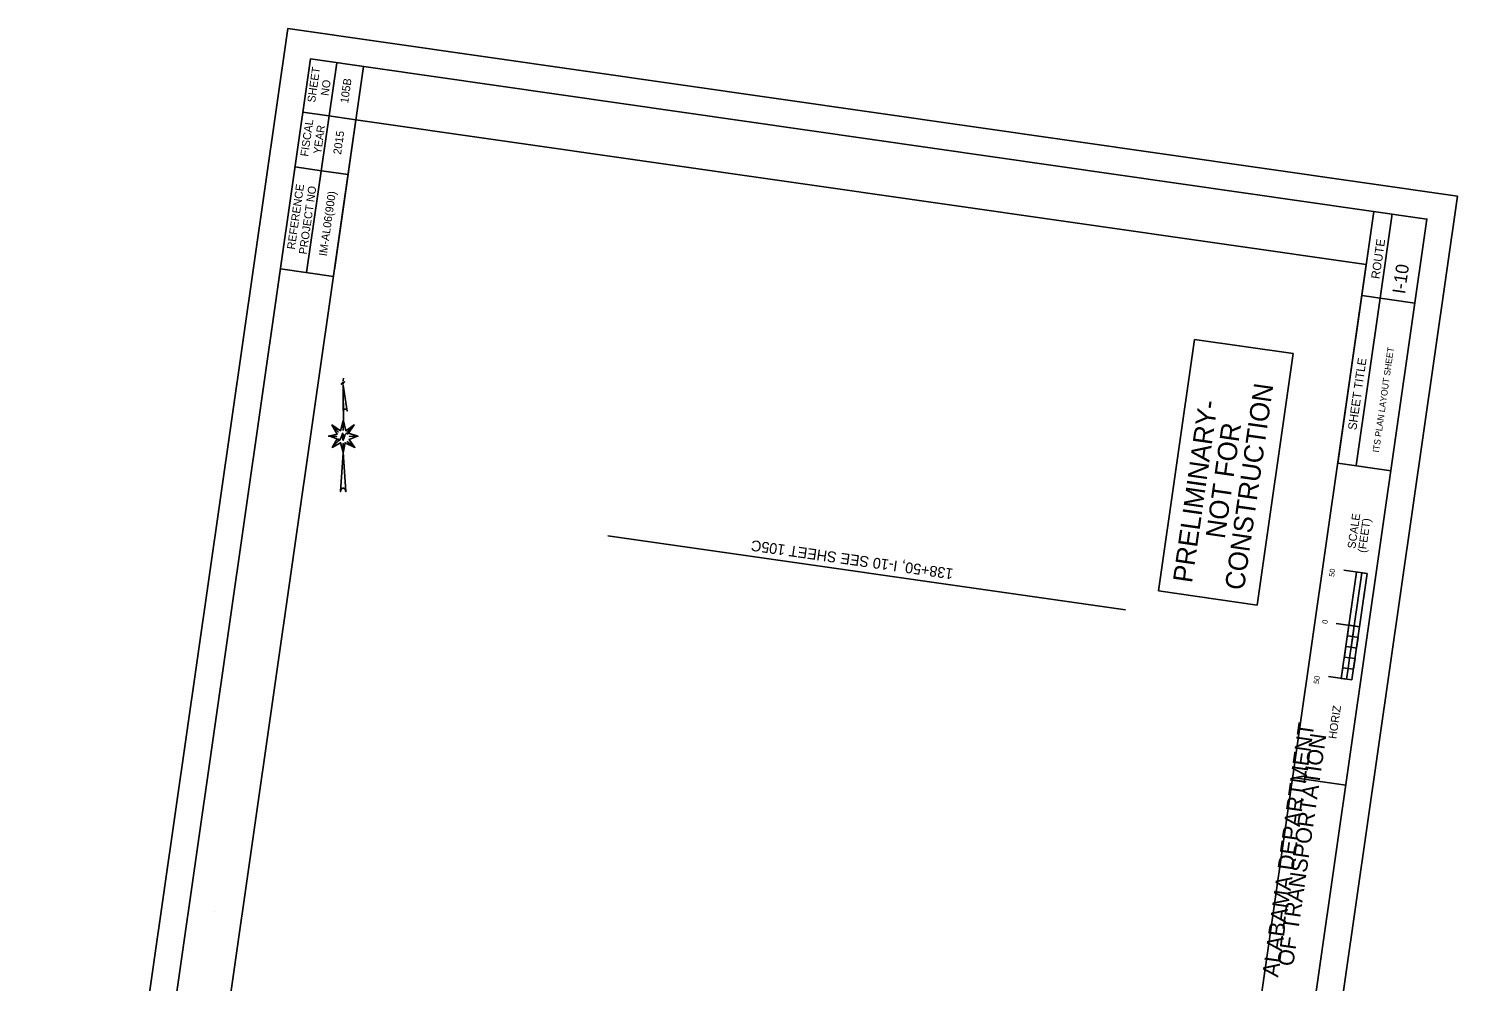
# Model space of a CAD drawing. Extents: x 1797106 to 1798436, y 247408 to 249247.
# Drawn here: x 1797106 to 1798436, y 248360 to 249247 of the extents above; entities that cross this region are included whole.
import ezdxf

# ---------------------------------------------------------------- set-up
doc = ezdxf.new("R2010")
doc.units = 0
for name, color, linetype in [('1', 7, 'Continuous'), ('29', 7, 'Continuous'), ('ANNO-SHT', 7, 'Continuous'), ('ANNO-SYMB', 7, 'Continuous'), ('ANNO-TXT', 7, 'Continuous'), ('DRAINAGE', 7, 'Continuous'), ('Level 1', 7, 'Continuous'), ('Level 57', 7, 'Continuous'), ('Level 6', 7, 'Continuous'), ('Level 62', 7, 'Continuous'), ('SHT-BDR', 7, 'Continuous'), ('SHT-BNDRY', 7, 'Continuous')]:
    doc.layers.add(name, color=color, linetype=linetype)

# ---------------------------------------------------------------- blocks, each defined once
blk = doc.blocks.new('SC47208')
at = {"layer": 'Level 1'}
blk.add_line((0, 0), (0, 0), dxfattribs=at)

msp = doc.modelspace()

# ---------------------------------------------------------------- linework, layer by layer
at = {"layer": '1'}
msp.add_lwpolyline([(1798158, 248723.5), (1798191.5, 248957.5), (1798283.2, 248944.4), (1798249.7, 248710.3)], close=True, dxfattribs=at)
at = {"layer": '29'}
msp.add_lwpolyline([(1797645.4, 248774.8), (1798127.1, 248706)], dxfattribs=at)
at = {"layer": 'ANNO-SYMB'}
for p, q in [((1798342.3, 248741), (1798328.1, 248642)), ((1798352.2, 248739.6), (1798330.4, 248742.7)), ((1798352.2, 248739.6), (1798338, 248640.6)), ((1798352.2, 248739.6), (1798347.3, 248740.3)), ((1798352.2, 248739.6), (1798347.3, 248740.3)), ((1798352.2, 248739.6), (1798347.3, 248740.3)), ((1798345.1, 248690.1), (1798323.3, 248693.2)), ((1798345.1, 248690.1), (1798323.3, 248693.2)), ((1798345.1, 248690.1), (1798323.3, 248693.2)), ((1798340.2, 248690.8), (1798335.2, 248691.5)), ((1798340.2, 248690.8), (1798335.2, 248691.5)), ((1798340.2, 248690.8), (1798335.2, 248691.5)), ((1798340.2, 248690.8), (1798337.3, 248671)), ((1798338, 248640.6), (1798316.3, 248643.8)), ((1798334.5, 248651.2), (1798329.5, 248651.9)), ((1798334.5, 248651.2), (1798329.5, 248651.9))]:
    msp.add_line(p, q, dxfattribs=at)
for points in [[(1798340.2, 248690.8), (1798347.3, 248740.3), (1798352.2, 248739.6), (1798345.1, 248690.1)], [(1798333.8, 248681.6), (1798335.2, 248691.5), (1798340.2, 248690.8), (1798338.8, 248680.9)], [(1798337.3, 248671), (1798338.8, 248680.9), (1798343.7, 248680.2), (1798342.3, 248670.3)], [(1798331, 248661.8), (1798332.4, 248671.7), (1798337.3, 248671), (1798335.9, 248661.1)], [(1798334.5, 248651.2), (1798335.9, 248661.1), (1798340.9, 248660.4), (1798339.4, 248650.5)], [(1798328.1, 248642), (1798329.5, 248651.9), (1798334.5, 248651.2), (1798333.1, 248641.3)]]:
    msp.add_lwpolyline(points, close=True, dxfattribs=at)
at = {"layer": 'ANNO-TXT'}
for p, q in [((1798364.4, 248996.1), (1798375.6, 249074.4)), ((1798342, 248840.1), (1798364.4, 248996.1))]:
    msp.add_line(p, q, dxfattribs=at)
at = {"layer": 'Level 57'}
msp.add_line((1797399.2, 248921.6), (1797399, 248919.1), dxfattribs=at)
for points in [[(1797400.3, 248918), (1797400.2, 248918), (1797400.2, 248917.8), (1797400.3, 248918), (1797400.3, 248918.1), (1797400.1, 248918.1), (1797399.8, 248918), (1797399.7, 248917.9), (1797399.5, 248917.5), (1797399.4, 248917.1), (1797399.1, 248916.5), (1797399.1, 248916.4), (1797399, 248916), (1797399, 248916.6), (1797398.9, 248917.5), (1797398.7, 248918.1), (1797398.7, 248917.5), (1797399, 248916), (1797398.9, 248917.5), (1797398.7, 248918.1), (1797398.6, 248917.6), (1797398.2, 248916.5), (1797397.9, 248916), (1797397.7, 248915.9), (1797397.4, 248915.9), (1797397.3, 248916), (1797397.3, 248916.2), (1797397.4, 248916.3), (1797397.5, 248916.2), (1797397.4, 248916.1)], [(1797399, 248915.1), (1797402.7, 248890.9), (1797402.6, 248891.7), (1797402.4, 248892), (1797402, 248892.3), (1797401.5, 248892.6), (1797401.1, 248892.6), (1797400.8, 248892.6), (1797400.4, 248892.7), (1797400.1, 248892.5), (1797399.8, 248892.4), (1797399.4, 248892.1), (1797399.2, 248891.9), (1797399.1, 248891.6), (1797399.1, 248891.4), (1797399.1, 248914.9), (1797399.2, 248882)], [(1797399.1, 248882), (1797399, 248873.1), (1797399.1, 248882.1), (1797396.4, 248872.5), (1797388.5, 248878), (1797394.6, 248871.3), (1797388.5, 248878), (1797393.5, 248869.5), (1797385.5, 248867.5), (1797393.1, 248867.3), (1797385.6, 248867.7), (1797393.3, 248864.9), (1797388.8, 248857), (1797394.5, 248862.8), (1797388.8, 248857), (1797396.6, 248861.4), (1797399, 248852.5), (1797398.9, 248860.8), (1797399, 248852.3), (1797401, 248861.3), (1797409.9, 248857.1), (1797400.9, 248861.3), (1797399, 248852), (1797396.6, 248816), (1797396.8, 248817.2), (1797397.1, 248818), (1797397.6, 248818.5), (1797398.2, 248818.9), (1797398.8, 248819), (1797399.4, 248819), (1797399.9, 248818.8), (1797400.4, 248818.5), (1797400.8, 248818), (1797401.2, 248817.4), (1797401.3, 248816.9), (1797401.5, 248816), (1797399.1, 248852.5), (1797400.8, 248861.4), (1797409.8, 248857.1), (1797403, 248862.4), (1797409.6, 248857.3), (1797404.5, 248864.3), (1797412.5, 248867.4), (1797404.8, 248867.3), (1797412.7, 248867.4), (1797403.9, 248870.2), (1797409.4, 248878), (1797403, 248871.7), (1797409.4, 248878), (1797401.4, 248872.5), (1797399.2, 248881.9)], [(1797403, 248870), (1797402.7, 248869.8), (1797403.1, 248869.5), (1797403.2, 248869.9), (1797403.1, 248870.2), (1797403, 248870.4), (1797402.3, 248870.3), (1797401.8, 248870), (1797400.7, 248868.8), (1797400.6, 248868.3), (1797400.3, 248867.1), (1797399.8, 248865.9), (1797399.3, 248865), (1797399.1, 248863.6), (1797399.1, 248865.4), (1797399, 248867.6), (1797398.9, 248868.8), (1797398.4, 248870.2), (1797398.3, 248868.5), (1797398.6, 248866.3), (1797398.8, 248864.8), (1797399.1, 248863.7), (1797399.1, 248865.7), (1797398.9, 248868.8), (1797398.3, 248870.3), (1797398, 248868.8), (1797397.4, 248867.2), (1797397.1, 248866.5), (1797396.9, 248865.7), (1797396.5, 248864.9), (1797396.2, 248864.4), (1797395.9, 248863.8), (1797395.1, 248863.5), (1797394.5, 248863.6), (1797394.2, 248863.9), (1797394.2, 248864.6), (1797394.6, 248864.9), (1797394.9, 248864.5), (1797394.6, 248864.3)]]:
    msp.add_lwpolyline(points, dxfattribs=at)
at = {"layer": 'Level 6'}
for p, q in [((1797393, 249215.2), (1797365, 249019.9)), ((1797418, 249211.6), (1797390.9, 249022.3)), ((1797385.6, 249165.7), (1797361.4, 249169.2)), ((1797385.6, 249165.7), (1797410.9, 249162.1)), ((1797378.9, 249114.7), (1797354.1, 249118.3)), ((1797378.9, 249114.7), (1797403.6, 249111.2)), ((1798358.4, 249076.8), (1798324.8, 248842.5)), ((1797340.6, 249023.4), (1797390, 249016.3))]:
    msp.add_line(p, q, dxfattribs=at)
at = {"layer": 'Level 62'}
msp.add_lwpolyline([(1798195, 247408.1), (1798436.2, 249090.9), (1797347.4, 249247), (1797106.2, 247564.2)], close=True, dxfattribs=at)
at = {"layer": 'SHT-BDR'}
msp.add_lwpolyline([(1798138.5, 247542.5), (1798351.3, 249027.3), (1797410.9, 249162.1), (1797198.1, 247677.3)], close=True, dxfattribs=at)
at = {"layer": 'SHT-BNDRY'}
for p, q in [((1798396.7, 248991.5), (1798347.2, 248998.6)), ((1798374.4, 248835.4), (1798324.8, 248842.5)), ((1798332.4, 248542.5), (1798282.8, 248549.6))]:
    msp.add_line(p, q, dxfattribs=at)
msp.add_lwpolyline([(1798179.2, 247473.5), (1798407.9, 249069.7), (1797368.6, 249218.7), (1797139.8, 247622.5)], close=True, dxfattribs=at)

# ---------------------------------------------------------------- block references
at = {"layer": 'DRAINAGE', "xscale": 1.0000020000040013, "yscale": 1.0000020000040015, "rotation": -34.57277348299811}
msp.add_blockref('SC47208', (1797279, 248425), dxfattribs=at)
msp.add_blockref('SC47208', (1797279, 248425), dxfattribs=at)

# ---------------------------------------------------------------- texts
at = {"layer": '1'}
for s, p in [('CONSTRUCTION', (1798237.4, 248723.4)), ('PRELIMINARY-', (1798189.1, 248730.3)), ('NOT FOR', (1798219.6, 248771.4))]:
    msp.add_text(s, height=18, rotation=81.8439, dxfattribs=at).set_placement(p)
at = {"layer": 'ANNO-SHT'}
for s, height, rotation, p in [('105B', 7.45, 81.8439, (1797403.6, 249177.1)), ('2015', 7.45, 81.8439, (1797397, 249129.3)), ('IM-AL06(900)', 7.449, 81.8439, (1797383.7, 249034.8)), ('  I-10  ', 12, 81.8439, (1798386.1, 248990.6)), ('ITS PLAN LAYOUT SHEET', 6, 81.8439, (1798363.2, 248852)), ('138+50, I-10 SEE SHEET 105C', 10, 171.8684, (1797967.5, 248744))]:
    msp.add_text(s, height=height, rotation=rotation, dxfattribs=at).set_placement(p)
at = {"layer": 'ANNO-SYMB'}
for s, height, p in [('SCALE', 7.5, (1798341.2, 248762.5)), ('(FEET)', 7.5, (1798350.9, 248758.6)), (' 50', 5, (1798321.2, 248734.4)), ('0', 5, (1798315.2, 248692.5)), ('0', 5, (1798315.2, 248692.5)), ('0', 5, (1798315.2, 248692.5)), (' 50', 5, (1798306.9, 248634.6)), ('HORIZ', 7.5, (1798323.5, 248585.3))]:
    msp.add_text(s, height=height, rotation=81.9011, dxfattribs=at).set_placement(p)
at = {"layer": 'ANNO-TXT'}
for s, height, p in [('ROUTE', 8, (1798363.7, 249013.5)), ('SHEET TITLE', 8, (1798342.1, 248872.8)), ('ALABAMA DEPARTMENT', 15, (1798269.3, 248363.3)), ('OF TRANSPORTATION', 15, (1798283.3, 248373.4))]:
    msp.add_text(s, height=height, rotation=81.8439, dxfattribs=at).set_placement(p)
at = {"layer": 'Level 6'}
for s, p in [('SHEET', (1797372.9, 249177.8)), ('NO', (1797385.4, 249184)), ('FISCAL', (1797366.4, 249127.5)), ('YEAR', (1797378.4, 249129.8)), ('REFERENCE', (1797354, 249041)), ('PROJECT NO', (1797365, 249036.4))]:
    msp.add_text(s, height=7.44, rotation=81.8439, dxfattribs=at).set_placement(p)

doc.saveas('drawing.dxf')
